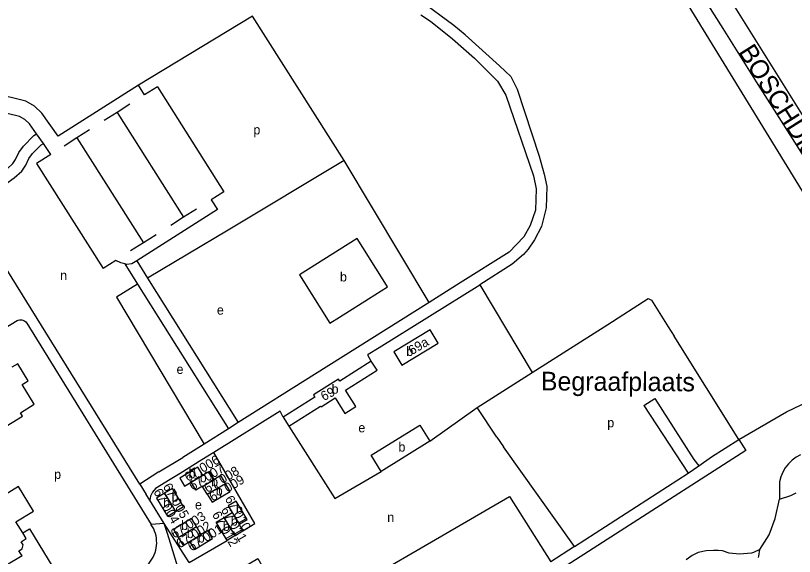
# Model space of a CAD drawing. Extents: x 158142 to 159655, y 385262 to 387204.
# Drawn here: x 158722.6 to 159056.3, y 386661 to 386892.7 of the extents above; entities that cross this region are included whole.
import ezdxf

# ---------------------------------------------------------------- set-up
doc = ezdxf.new("R2010")
doc.units = 0
for name, color, linetype in [('BLT_Basislijn', 7, 'Continuous'), ('BLT_Bebouwing', 7, 'Continuous'), ('BLT_Centroide', 7, 'Continuous'), ('BLT_Huisnummer', 7, 'Continuous'), ('BLT_Onderverdeling_panden', 7, 'Continuous'), ('BLT_Straatnaam', 7, 'Continuous'), ('BLT_Terrein_beschrifting', 7, 'Continuous'), ('BLT_Vlakafsluiter', 7, 'Continuous')]:
    doc.layers.add(name, color=color, linetype=linetype)

msp = doc.modelspace()

# ---------------------------------------------------------------- linework, layer by layer
at = {"layer": 'BLT_Basislijn'}
for p, q in [((158783.33, 386862.18), (158777.86, 386858.7)), ((158783.33, 386862.18), (158811.87, 386817.24)), ((158771.53, 386854.69), (158766.06, 386851.21)), ((158766.06, 386851.21), (158760.6, 386847.74)), ((158766.06, 386851.21), (158794.6, 386806.28)), ((158754.27, 386843.72), (158748.8, 386840.25)), ((158748.8, 386840.25), (158743.33, 386836.77)), ((158748.8, 386840.25), (158777.34, 386795.31)), ((158737.7, 386833.19), (158731.54, 386829.28)), ((158731.54, 386829.28), (158760.08, 386784.35)), ((158811.87, 386817.24), (158806.4, 386813.77)), ((158775.77, 386691.97), (158702.96, 386809.4)), ((158800.07, 386809.75), (158794.6, 386806.28)), ((158794.6, 386806.28), (158789.14, 386802.8)), ((158782.81, 386798.79), (158777.34, 386795.31)), ((158777.34, 386795.31), (158771.87, 386791.84)), ((158765.55, 386787.82), (158760.08, 386784.35)), ((158769.36, 386786.3), (158774.86, 386777.56)), ((158774.47, 386787.57), (158779.15, 386780.13)), ((158779.15, 386780.13), (158818.02, 386718.34)), ((158774.86, 386777.56), (158813.79, 386715.67)), ((158878.32, 386750.5), (158921.47, 386777.32)), ((158913.14, 386778.2), (158899.79, 386769.8)), ((158921.47, 386777.32), (158943.92, 386739.81)), ((158899.79, 386769.8), (158850.7, 386738.9)), ((158706.46, 386752.08), (158723.25, 386762.04)), ((158727.38, 386760.9), (158780.64, 386674.69)), ((159002.27, 386759.37), (159004.8, 386755.37)), ((159032.59, 386711.15), (159004.8, 386755.37)), ((158850.7, 386738.9), (158818.02, 386718.34)), ((158991.88, 386725.63), (158996.59, 386728.61)), ((158991.88, 386725.63), (159010.87, 386696.67)), ((158813.79, 386715.67), (158803.43, 386709.15)), ((158818.02, 386718.34), (158813.79, 386715.67)), ((158839.69, 386716.76), (158859.4, 386685.87)), ((158928.76, 386712.13), (158931.68, 386707.97)), ((158803.43, 386709.15), (158794.2, 386703.34)), ((158962.1, 386665.28), (158931.68, 386707.97)), ((158784.02, 386697.2), (158794.2, 386703.34)), ((158802.34, 386702.38), (158793.09, 386696.61)), ((159010.87, 386696.67), (159015.33, 386699.77)), ((158784.02, 386697.2), (158775.77, 386691.97)), ((158859.4, 386685.87), (158879.3, 386697.4)), ((158962.1, 386665.28), (159010.87, 386696.67)), ((158788.87, 386693.98), (158782.59, 386690.07)), ((158780.05, 386685.17), (158778.57, 386687.56)), ((158786.24, 386675.16), (158780.05, 386685.17)), ((158796.96, 386658.41), (158786.24, 386675.16)), ((158725.61, 386671.11), (158728.49, 386672.91)), ((158728.49, 386672.91), (158747.01, 386642.5)), ((158796.96, 386658.41), (158813.21, 386667.91)), ((158962.1, 386665.28), (158951.94, 386658.76))]:
    msp.add_line(p, q, dxfattribs=at)
for points in [[(159103.65, 386742.39), (159099.94, 386748.36), (159098.83, 386750), (159091.4, 386761.9), (159082.06, 386777.82), (159078.59, 386786.94), (159064.74, 386809.3), (158958.42, 386982.75)], [(159083.22, 386795.27), (159074.66, 386809.4), (159063.45, 386827.49), (159040.75, 386863.13), (159025.87, 386887.16), (158965.29, 386982.75)], [(159089.59, 386802.28), (159073.79, 386827.75), (159023.04, 386908.93), (158995.81, 386951.04), (158976.07, 386982.75)], [(158929.94, 386871.18), (158915.21, 386884.4), (158910.37, 386888.39), (158895.73, 386899.33)], [(158863.44, 386830.56), (158824.16, 386892.39), (158775.18, 386862.92)], [(158896.27, 386892.92), (158900.34, 386890.22), (158909.81, 386882.69), (158919.27, 386874.47), (158929.05, 386864.56), (158932.64, 386858.61), (158944.48, 386824.01), (158945.66, 386818.41), (158945.43, 386809.38), (158943.15, 386802.81), (158940.34, 386797.93), (158934.04, 386791.34), (158913.14, 386778.2)], [(158929.94, 386871.18), (158934.84, 386866.63), (158937.57, 386861.16), (158946.91, 386832.44), (158949.04, 386824.76), (158950.17, 386819.45), (158950.01, 386810.36), (158947.97, 386802.29), (158944.94, 386796.57), (158942.21, 386792.62), (158940.17, 386790.36), (158935.42, 386786.26), (158921.47, 386777.32)], [(158740.75, 386841.06), (158733.89, 386850.93), (158730.75, 386853.84), (158726.94, 386856.05), (158720.61, 386857.61), (158694.72, 386863.26)], [(158775.18, 386862.92), (158740.75, 386841.06)], [(158777.86, 386858.7), (158775.18, 386862.92)], [(158731.6, 386841.96), (158728.58, 386846.31), (158726.56, 386848.18), (158724.3, 386849.49), (158719.03, 386850.79), (158696.95, 386855.61), (158693.92, 386855.92), (158692.49, 386855.5), (158688.28, 386852.84)], [(158700.33, 386813.65), (158707.59, 386818.35), (158710.25, 386821.06), (158718.92, 386827.06), (158721.46, 386829.32), (158722.54, 386831.03), (158723.97, 386834.01), (158725.96, 386836.75), (158730.43, 386841.33), (158731.6, 386841.96)], [(158734.47, 386837.83), (158731.6, 386841.96)], [(158702.96, 386809.4), (158710.77, 386814.45), (158713.48, 386817.21), (158722.02, 386823.12), (158725.31, 386826.06), (158726.92, 386828.6), (158728.28, 386831.44), (158729.79, 386833.52), (158733.48, 386837.29), (158734.47, 386837.83)], [(158737.7, 386833.19), (158734.47, 386837.83)], [(158863.44, 386830.56), (158813.67, 386800.78)], [(158899.79, 386769.8), (158863.44, 386830.56)], [(158806.4, 386813.77), (158809.08, 386809.55), (158774.47, 386787.57)], [(158813.67, 386800.78), (158779.15, 386780.13)], [(158769.36, 386786.3), (158767.71, 386786.74), (158765.55, 386787.82)], [(158774.47, 386787.57), (158772.33, 386786.28), (158770.24, 386786.07), (158769.36, 386786.3)], [(158774.86, 386777.56), (158765.76, 386772.12), (158803.43, 386709.15)], [(158976.36, 386760.39), (158993.71, 386771.48), (158995.05, 386770.75), (159002.27, 386759.37)], [(158723.25, 386762.04), (158723.71, 386762.23), (158724.2, 386762.35), (158724.7, 386762.4), (158725.2, 386762.36), (158725.68, 386762.24), (158726.14, 386762.05), (158726.57, 386761.78), (158726.95, 386761.46), (158727.27, 386761.07), (158727.38, 386760.9)], [(158943.92, 386739.81), (158976.36, 386760.39)], [(158875, 386744.65), (158873.7, 386746.96), (158873.69, 386747.62), (158878.32, 386750.5)], [(159032.59, 386711.15), (159053, 386722.91), (159074.25, 386733.11), (159088.84, 386737.48), (159097.73, 386738.7), (159103.65, 386742.39)], [(158920.36, 386724.87), (158943.92, 386739.81)], [(158996.59, 386728.61), (159013.26, 386702.51), (159015.33, 386699.77)], [(158837.23, 386720.67), (158835.92, 386723.3), (158807.51, 386705.6)], [(158900.1, 386710.42), (158920.36, 386724.87)], [(158928.76, 386712.13), (158920.36, 386724.87)], [(159032.59, 386711.15), (159035.58, 386706.39), (158927.86, 386637.32), (158917.44, 386630.31), (158916.87, 386628.46), (158918.23, 386626.84), (158919.19, 386626.73), (158929.27, 386628.01), (158936.03, 386627.86), (158952.13, 386627.33), (158964.14, 386625.61), (158979.12, 386621.87), (159000.33, 386614.38), (159008.02, 386609.31)], [(159015.33, 386699.77), (159020.84, 386703.65), (159032.59, 386711.15)], [(158807.51, 386705.6), (158802.34, 386702.38)], [(158820.02, 386672), (158825.07, 386675.18), (158807.51, 386705.6)], [(159059, 386704.48), (159057.14, 386703.47), (159055.39, 386702.19), (159053.81, 386700.67), (159052.44, 386698.94), (159051.33, 386697.04), (159050.49, 386695.05), (159049.93, 386693), (159049.93, 386685.6)], [(158793.09, 386696.61), (158788.87, 386693.98)], [(158782.59, 386690.07), (158781.21, 386688.52), (158780.33, 386686.83), (158780.05, 386685.17)], [(158800.5, 386644.91), (158826.35, 386660.11), (158841.79, 386632.99), (158934.18, 386686.67), (158951.94, 386658.76)], [(159041.5, 386664), (159045.5, 386670.27), (159048.12, 386677.23), (159049.93, 386685.6)], [(159049.93, 386685.6), (159054.78, 386687.06), (159057.09, 386688.2)], [(158789, 386666.64), (158787.61, 386670.82), (158786.24, 386675.16)], [(158777.49, 386656.07), (158778.31, 386656.71), (158779.07, 386657.42), (158779.78, 386658.18), (158780.43, 386658.99), (158781.01, 386659.85), (158781.52, 386660.75), (158781.97, 386661.69), (158782.34, 386662.66), (158782.64, 386663.66), (158782.85, 386664.68), (158782.99, 386665.71), (158783.05, 386666.74), (158783.03, 386667.78), (158782.93, 386668.82), (158782.75, 386669.84), (158782.49, 386670.85), (158782.16, 386671.83), (158781.75, 386672.79), (158781.27, 386673.71), (158780.72, 386674.59), (158780.64, 386674.69)], [(158796.42, 386642.36), (158789, 386666.64)], [(159041.5, 386664), (159038.82, 386662.76), (159037.92, 386662.45), (159032.78, 386661.94), (159028.4, 386662.48), (159025.56, 386663.4), (159023.7, 386663.56), (159021.72, 386663.54), (159018.53, 386663.46), (159015.14, 386662.64), (159012.56, 386661.36), (159009.93, 386659.58)], [(159040.99, 386660.5), (159041.1, 386661.07), (159041.5, 386664)]]:
    msp.add_lwpolyline(points, dxfattribs=at)
at = {"layer": 'BLT_Bebouwing'}
for p, q in [((158863.7, 386722.23), (158868.4, 386725.19)), ((158900.1, 386710.42), (158879.3, 386697.4)), ((158804.7, 386687.68), (158802.69, 386691)), ((158811.95, 386677.72), (158815.36, 386679.77)), ((158802.1, 386670.44), (158800.05, 386673.83)), ((158816.62, 386669.95), (158820.02, 386672)), ((158820.02, 386672), (158818.34, 386674.8)), ((158816.62, 386669.95), (158813.21, 386667.91))]:
    msp.add_line(p, q, dxfattribs=at)
msp.add_lwpolyline([(158844.27, 386781.59), (158849.54, 386773.22), (158857.29, 386760.92), (158861.45, 386763.54), (158873.76, 386771.3), (158882, 386776.49), (158879.37, 386780.65), (158868.97, 386797.12)], close=True, dxfattribs=at)
for points in [[(158903.7, 386752.35), (158900.27, 386758.04), (158884.7, 386748.67)], [(158884.7, 386748.67), (158888.15, 386742.99), (158903.7, 386752.35)], [(158716.61, 386715.72), (158725.52, 386721.16), (158724.67, 386722.58), (158730.55, 386726.18), (158725.41, 386734.67), (158727.96, 386736.25), (158723.49, 386743.57), (158720.91, 386742.05)], [(158875, 386744.65), (158861.47, 386736.06), (158860.9, 386736.95), (158850.26, 386730.2), (158850.83, 386729.3), (158837.23, 386720.67)], [(158868.4, 386725.19), (158863.96, 386732.23), (158877.46, 386740.74), (158875, 386744.65)], [(158839.69, 386716.76), (158853.31, 386725.35), (158853.48, 386725.08), (158859.5, 386728.88), (158863.7, 386722.23)], [(158837.23, 386720.67), (158839.69, 386716.76)], [(158879.3, 386697.4), (158874.97, 386704.33), (158895.82, 386717.3), (158900.1, 386710.42)], [(158802.79, 386695.77), (158800.72, 386699.23), (158792.95, 386694.59), (158794.99, 386691.18), (158797.8, 386692.87), (158797.84, 386692.81)], [(158807.68, 386693.98), (158805.61, 386697.45), (158802.79, 386695.77)], [(158812.52, 386692.26), (158810.49, 386695.66), (158807.68, 386693.98)], [(158802.69, 386691), (158802.63, 386691.1), (158799.86, 386689.41), (158797.84, 386692.81)], [(158804.7, 386687.68), (158806.76, 386684.26), (158814.55, 386688.86), (158812.52, 386692.26)], [(158725.61, 386671.11), (158722.75, 386675.8), (158730.29, 386680.38), (158723.84, 386690.97), (158711.71, 386683.51), (158707.98, 386689.64)], [(158791.1, 386680.33), (158794.52, 386682.4), (158789.88, 386690.13), (158786.42, 386688.07)], [(158786.42, 386688.07), (158783.03, 386686.04), (158787.69, 386678.27), (158791.1, 386680.33)], [(158818.34, 386674.8), (158821.79, 386676.87), (158817.12, 386684.63), (158813.74, 386682.63), (158815.46, 386679.83), (158815.36, 386679.77)], [(158800.05, 386673.83), (158797.99, 386677.22), (158790.23, 386672.52), (158792.28, 386669.13)], [(158813.21, 386667.91), (158808.54, 386675.68), (158811.95, 386677.72)], [(158797.13, 386667.43), (158799.21, 386664), (158806.97, 386668.7), (158804.9, 386672.14), (158802.1, 386670.44)], [(158725.33, 386661.29), (158724.03, 386663.42), (158725.36, 386664.24), (158725.78, 386666.03), (158724.98, 386667.34), (158727.11, 386668.65), (158725.61, 386671.11)], [(158792.28, 386669.13), (158794.33, 386665.74), (158797.13, 386667.43)], [(158725.33, 386661.29), (158717.94, 386656.78), (158716.61, 386658.87), (158715.3, 386658.1), (158713.66, 386658.48), (158708.76, 386655.49), (158708.35, 386653.84), (158707.05, 386653.03), (158708.34, 386650.9)]]:
    msp.add_lwpolyline(points, dxfattribs=at)
at = {"layer": 'BLT_Onderverdeling_panden'}
for p, q in [((158797.84, 386692.81), (158802.79, 386695.77)), ((158802.69, 386691), (158807.68, 386693.98)), ((158804.7, 386687.68), (158812.52, 386692.26)), ((158786.42, 386688.07), (158791.1, 386680.33)), ((158815.36, 386679.77), (158818.34, 386674.8)), ((158816.62, 386669.95), (158811.95, 386677.72)), ((158792.28, 386669.13), (158800.05, 386673.83)), ((158797.13, 386667.43), (158802.1, 386670.44))]:
    msp.add_line(p, q, dxfattribs=at)
at = {"layer": 'BLT_Vlakafsluiter'}
for p, q in [((158775.77, 386691.97), (158778.57, 386687.56)), ((158786.24, 386675.16), (158780.64, 386674.69))]:
    msp.add_line(p, q, dxfattribs=at)

# ---------------------------------------------------------------- texts
at = {"layer": 'BLT_Centroide'}
for s, p in [('p', (158824.47, 386841.77)), ('n', (158741.67, 386779.42)), ('b', (158861.59, 386778.79)), ('e', (158808.84, 386764.58)), ('b', (158890.02, 386746.89)), ('e', (158791.55, 386739.2)), ('b', (158857.99, 386730.72)), ('p', (158976.14, 386716.33)), ('e', (158869.46, 386714.17)), ('b', (158886.65, 386705.92)), ('b', (158796.71, 386694.47)), ('p', (158739.1, 386694.22)), ('b', (158801.47, 386692.8)), ('b', (158806.38, 386691.03)), ('b', (158789.42, 386684.51)), ('b', (158808.36, 386687.16)), ('b', (158785.76, 386682.02)), ('e', (158799.44, 386681.16)), ('b', (158816.99, 386679.3)), ('b', (158814.81, 386674.21)), ('n', (158881.84, 386675.81)), ('b', (158793.5, 386672.34)), ('b', (158811.39, 386671.95)), ('b', (158795.91, 386668.88)), ('b', (158800.66, 386666.97))]:
    msp.add_text(s, height=4, dxfattribs=at).set_placement(p)
at = {"layer": 'BLT_Huisnummer'}
for s, rotation, p in [('69a', 31.0302, (158892.41, 386747.16)), ('69', 27.8253, (158854.65, 386727.51)), ('67 006', 30.8252, (158796.44, 386692.91)), ('67 007', 30.8252, (158798.38, 386689.15)), ('67 008', 30.8252, (158804.8, 386688.13)), ('67 009', 30.8252, (158807.06, 386684.42)), ('67 005', 299.8252, (158785.55, 386691)), ('67 004', 299.8252, (158781.5, 386688.73)), ('67 010', 299.8252, (158812.11, 386685.71)), ('67 011', 299.8252, (158810.44, 386681.02)), ('67 003', 31.8253, (158790.61, 386668.57)), ('67 012', 299.8252, (158806.64, 386678.99)), ('67 002', 31.8253, (158792.99, 386664.38)), ('67 001', 31.8253, (158797.94, 386663.09))]:
    msp.add_text(s, height=4, rotation=rotation, dxfattribs=at).set_placement(p)
at = {"layer": 'BLT_Straatnaam'}
msp.add_text('BOSCHDIJK', height=8, rotation=302.2071, dxfattribs=at).set_placement((159032.06, 386877.14))
at = {"layer": 'BLT_Terrein_beschrifting'}
msp.add_text('Begraafplaats', height=8, rotation=359.6436, dxfattribs=at).set_placement((158947.65, 386732.14))

doc.saveas('drawing.dxf')
